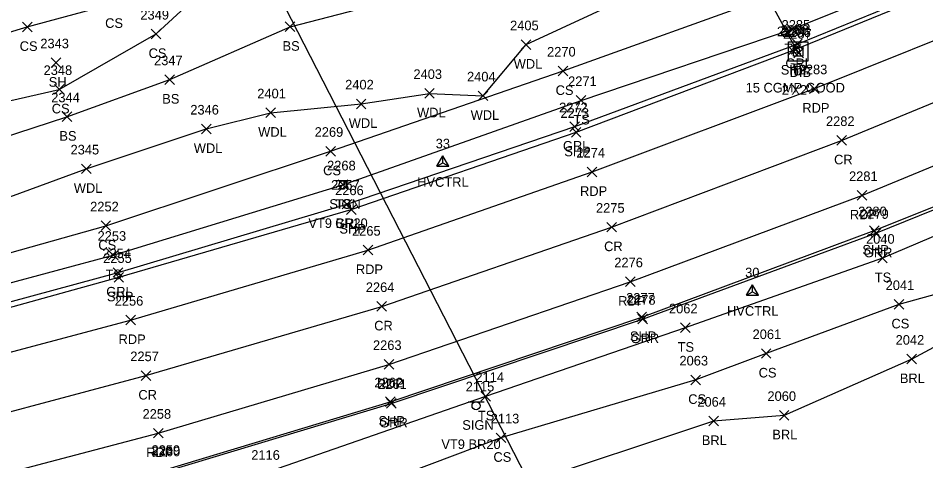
# Model space of a CAD drawing. Extents: x 1502194 to 1507887, y 142265 to 144150.
# Drawn here: x 1506653.1 to 1506842, y 143470.6 to 143562.8 of the extents above; entities that cross this region are included whole.
import ezdxf

# ---------------------------------------------------------------- set-up
doc = ezdxf.new("R2010")
doc.units = 0
for name, color, linetype in [('C_A', 7, 'Continuous'), ('C_I', 7, 'Continuous'), ('CPSM', 7, 'Continuous'), ('D_A', 7, 'Continuous'), ('D_C', 7, 'Continuous'), ('D_I', 7, 'Continuous'), ('D_TIC', 7, 'Continuous'), ('DCP', 7, 'Continuous'), ('DS', 7, 'Continuous'), ('L_A', 7, 'Continuous'), ('L_I', 7, 'Continuous'), ('L_TIC', 7, 'Continuous'), ('LABL', 7, 'Continuous'), ('LAWA', 7, 'Continuous'), ('LELB', 7, 'Continuous'), ('P_A', 7, 'Continuous'), ('P_I', 7, 'Continuous'), ('P_TIC', 7, 'Continuous'), ('PET', 7, 'Continuous'), ('PRC', 7, 'Continuous'), ('PSP', 7, 'Continuous'), ('R_A', 7, 'Continuous'), ('R_I', 7, 'Continuous'), ('R_TIC', 7, 'Continuous'), ('RGR', 7, 'Continuous'), ('S_A', 7, 'Continuous'), ('S_C', 7, 'Continuous'), ('S_I', 7, 'Continuous'), ('SSGN', 7, 'Continuous')]:
    doc.layers.add(name, color=color, linetype=linetype)

msp = doc.modelspace()

# ---------------------------------------------------------------- linework, layer by layer
at = {"layer": 'CPSM'}
for p, q in [((1506740.16, 143531.98), (1506741.41, 143534.15)), ((1506742.66, 143531.98), (1506741.41, 143534.15)), ((1506741.41, 143532.7), (1506741.41, 143534.15)), ((1506740.16, 143531.98), (1506741.41, 143532.7)), ((1506740.16, 143531.98), (1506742.66, 143531.98)), ((1506741.41, 143532.7), (1506741.41, 143532.7)), ((1506741.41, 143532.7), (1506742.66, 143531.98)), ((1506804.65, 143505.13), (1506805.9, 143507.3)), ((1506807.15, 143505.13), (1506805.9, 143507.3)), ((1506805.9, 143505.85), (1506805.9, 143507.3)), ((1506804.65, 143505.13), (1506805.9, 143505.85)), ((1506805.9, 143505.85), (1506805.9, 143505.85)), ((1506805.9, 143505.85), (1506807.15, 143505.13)), ((1506804.65, 143505.13), (1506807.15, 143505.13))]:
    msp.add_line(p, q, dxfattribs=at)
at = {"layer": 'D_TIC'}
for points in [[(1506813.95, 143555.34), (1506815.95, 143557.34)], [(1506815.95, 143555.34), (1506813.95, 143557.34)], [(1506814.51, 143554.57), (1506816.51, 143556.57)], [(1506816.51, 143554.57), (1506814.51, 143556.57)]]:
    msp.add_lwpolyline(points, dxfattribs=at)
at = {"layer": 'DCP'}
for points in [[(1506814.95, 143556.34), (1506782.88, 143615.38)], [(1506777.4, 143431.12), (1506698.03, 143585.85)]]:
    msp.add_lwpolyline(points, dxfattribs=at)
at = {"layer": 'DS'}
for p, q in [((1506813.38, 143557.88), (1506817.38, 143557.88)), ((1506813.38, 143553.88), (1506813.38, 143557.88)), ((1506814.38, 143554.88), (1506814.38, 143556.88)), ((1506814.38, 143556.88), (1506816.38, 143556.88)), ((1506816.38, 143556.88), (1506816.38, 143554.88)), ((1506817.38, 143557.88), (1506817.38, 143553.88)), ((1506816.38, 143554.88), (1506814.38, 143554.88)), ((1506815.39, 143555.88), (1506815.39, 143555.88)), ((1506815.39, 143555.88), (1506815.39, 143555.88)), ((1506817.38, 143553.88), (1506813.38, 143553.88))]:
    msp.add_line(p, q, dxfattribs=at)
at = {"layer": 'L_TIC'}
for points in [[(1506653.94, 143560), (1506655.94, 143562)], [(1506655.94, 143560), (1506653.94, 143562)], [(1506708.64, 143560.03), (1506710.64, 143562.03)], [(1506710.64, 143560.03), (1506708.64, 143562.03)], [(1506680.76, 143558.52), (1506682.76, 143560.52)], [(1506682.76, 143558.52), (1506680.76, 143560.52)], [(1506813.12, 143559.53), (1506815.12, 143561.53)], [(1506815.12, 143559.53), (1506813.12, 143561.53)], [(1506757.77, 143556.3), (1506759.77, 143558.3)], [(1506759.77, 143556.3), (1506757.77, 143558.3)], [(1506659.93, 143552.54), (1506661.93, 143554.54)], [(1506661.93, 143552.54), (1506659.93, 143554.54)], [(1506765.47, 143550.82), (1506767.47, 143552.82)], [(1506767.47, 143550.82), (1506765.47, 143552.82)], [(1506683.6, 143549.02), (1506685.6, 143551.02)], [(1506685.6, 143549.02), (1506683.6, 143551.02)], [(1506660.61, 143546.98), (1506662.61, 143548.98)], [(1506662.61, 143546.98), (1506660.61, 143548.98)], [(1506737.66, 143546.16), (1506739.66, 143548.16)], [(1506739.66, 143546.16), (1506737.66, 143548.16)], [(1506748.81, 143545.64), (1506750.81, 143547.64)], [(1506750.81, 143545.64), (1506748.81, 143547.64)], [(1506723.44, 143543.97), (1506725.44, 143545.97)], [(1506725.44, 143543.97), (1506723.44, 143545.97)], [(1506769.21, 143544.68), (1506771.21, 143546.68)], [(1506771.21, 143544.68), (1506769.21, 143546.68)], [(1506662.2, 143541.3), (1506664.2, 143543.3)], [(1506664.2, 143541.3), (1506662.2, 143543.3)], [(1506704.6, 143542.12), (1506706.6, 143544.12)], [(1506706.6, 143542.12), (1506704.6, 143544.12)], [(1506691.19, 143538.75), (1506693.19, 143540.75)], [(1506693.19, 143538.75), (1506691.19, 143540.75)], [(1506717.08, 143534.11), (1506719.08, 143536.11)], [(1506719.08, 143534.11), (1506717.08, 143536.11)], [(1506666.22, 143530.44), (1506668.22, 143532.44)], [(1506668.22, 143530.44), (1506666.22, 143532.44)], [(1506719.65, 143527.12), (1506721.65, 143529.12)], [(1506721.65, 143527.12), (1506719.65, 143529.12)], [(1506670.3, 143518.58), (1506672.3, 143520.58)], [(1506672.3, 143518.58), (1506670.3, 143520.58)], [(1506671.84, 143512.46), (1506673.84, 143514.46)], [(1506673.84, 143512.46), (1506671.84, 143514.46)], [(1506831.93, 143511.84), (1506833.93, 143513.84)], [(1506833.93, 143511.84), (1506831.93, 143513.84)], [(1506835.36, 143502.21), (1506837.36, 143504.21)], [(1506837.36, 143502.21), (1506835.36, 143504.21)], [(1506790.89, 143497.35), (1506792.89, 143499.35)], [(1506792.89, 143497.35), (1506790.89, 143499.35)], [(1506807.72, 143491.99), (1506809.72, 143493.99)], [(1506809.72, 143491.99), (1506807.72, 143493.99)], [(1506838.01, 143490.82), (1506840.01, 143492.82)], [(1506840.01, 143490.82), (1506838.01, 143492.82)], [(1506793.07, 143486.49), (1506795.07, 143488.49)], [(1506795.07, 143486.49), (1506793.07, 143488.49)], [(1506749.34, 143483.06), (1506751.34, 143485.06)], [(1506751.34, 143483.06), (1506749.34, 143485.06)], [(1506811.47, 143479.11), (1506813.47, 143481.11)], [(1506813.47, 143479.11), (1506811.47, 143481.11)], [(1506796.79, 143477.92), (1506798.79, 143479.92)], [(1506798.79, 143477.92), (1506796.79, 143479.92)], [(1506752.53, 143474.43), (1506754.53, 143476.43)], [(1506754.53, 143474.43), (1506752.53, 143476.43)]]:
    msp.add_lwpolyline(points, dxfattribs=at)
at = {"layer": 'LABL'}
msp.add_lwpolyline([(1506925.15, 143533.52), (1506885.27, 143516.72), (1506839.01, 143491.82), (1506812.47, 143480.11), (1506797.79, 143478.92), (1506756.88, 143465.31), (1506714.98, 143450.06), (1506660.24, 143438.77), (1506613.3, 143423.94), (1506616.52, 143414.64)], dxfattribs=at)
at = {"layer": 'LAWA'}
msp.add_lwpolyline([(1506522.71, 143485.76), (1506572.06, 143503.17), (1506623.68, 143515.47), (1506667.22, 143531.44), (1506692.19, 143539.75), (1506705.6, 143543.12), (1506724.44, 143544.97), (1506738.66, 143547.16), (1506749.81, 143546.64), (1506758.77, 143557.3), (1506807.57, 143579.94), (1506846.79, 143592.4), (1506896.99, 143614.38)], dxfattribs=at)
at = {"layer": 'LELB'}
for points in [[(1506624.13, 143555.62), (1506640.38, 143556.63), (1506654.94, 143561), (1506672.72, 143565.79), (1506679.72, 143575.67), (1506695.05, 143577.62), (1506699.47, 143577.91), (1506701.5, 143575.19), (1506703.76, 143575.39), (1506707.13, 143577.97), (1506705.55, 143581.26), (1506716.61, 143587.23), (1506735.68, 143602.47), (1506756.62, 143603.39), (1506780.29, 143609.03), (1506830.83, 143625.99), (1506880.34, 143648.95)], [(1506517.85, 143501.34), (1506567.89, 143522.62), (1506612.11, 143536.7), (1506661.61, 143547.98), (1506681.76, 143559.52), (1506695.53, 143572.24), (1506704.85, 143572.91), (1506725.52, 143573.91), (1506746.5, 143587.18), (1506797.75, 143604.14), (1506837.79, 143614.31), (1506888.27, 143631.28)], [(1506520.26, 143493.12), (1506571.84, 143512.42), (1506617.89, 143527.46), (1506663.2, 143542.3), (1506684.6, 143550.02), (1506709.64, 143561.03), (1506743.74, 143569.88), (1506756.3, 143575.97), (1506802.67, 143594.79), (1506845.42, 143601.65), (1506896.99, 143614.38)], [(1506527.12, 143479.02), (1506576.48, 143493.75), (1506624.1, 143506.32), (1506671.3, 143519.58), (1506718.08, 143535.11), (1506766.47, 143551.82), (1506810.91, 143567.85), (1506852.21, 143584.27), (1506899, 143603.69)], [(1506528.28, 143476.03), (1506576.44, 143487.76), (1506625.32, 143500.66), (1506672.84, 143513.46), (1506720.65, 143528.12), (1506770.21, 143545.68), (1506814.12, 143560.53), (1506853.98, 143576.57), (1506901.25, 143597.01)], [(1506920.49, 143550.15), (1506879.81, 143532.73), (1506832.93, 143512.84), (1506791.89, 143498.35), (1506750.34, 143484.06), (1506703.75, 143467.85), (1506654.25, 143455.79), (1506605.88, 143441.31), (1506565.5, 143431.73), (1506554.53, 143418.24), (1506550.8, 143411.14), (1506553.36, 143401.15), (1506568.06, 143393.58), (1506589.98, 143377.59)], [(1506885.27, 143516.72), (1506836.36, 143503.21), (1506808.72, 143492.99), (1506794.07, 143487.49), (1506753.53, 143475.43), (1506709.32, 143458.78), (1506657.01, 143447.54), (1506608.42, 143435.74), (1506565.83, 143422.65), (1506556.41, 143414.68), (1506554.63, 143405.1), (1506570.25, 143400.38), (1506594.37, 143381.91)]]:
    msp.add_lwpolyline(points, dxfattribs=at)
at = {"layer": 'P_TIC'}
for points in [[(1506813.23, 143555.06), (1506815.23, 143557.06)], [(1506815.23, 143555.06), (1506813.23, 143557.06)], [(1506817.76, 143547.14), (1506819.76, 143549.14)], [(1506819.76, 143547.14), (1506817.76, 143549.14)], [(1506768.18, 143538.06), (1506770.18, 143540.06)], [(1506770.18, 143538.06), (1506768.18, 143540.06)], [(1506823.43, 143536.37), (1506825.43, 143538.37)], [(1506825.43, 143536.37), (1506823.43, 143538.37)], [(1506771.5, 143529.8), (1506773.5, 143531.8)], [(1506773.5, 143529.8), (1506771.5, 143531.8)], [(1506827.66, 143524.9), (1506829.66, 143526.9)], [(1506829.66, 143524.9), (1506827.66, 143526.9)], [(1506721.38, 143521.96), (1506723.38, 143523.96)], [(1506723.38, 143521.96), (1506721.38, 143523.96)], [(1506775.57, 143518.3), (1506777.57, 143520.3)], [(1506777.57, 143518.3), (1506775.57, 143520.3)], [(1506830.22, 143517.57), (1506832.22, 143519.57)], [(1506832.22, 143517.57), (1506830.22, 143519.57)], [(1506724.85, 143513.52), (1506726.85, 143515.52)], [(1506726.85, 143513.52), (1506724.85, 143515.52)], [(1506673.01, 143507.85), (1506675.01, 143509.85)], [(1506675.01, 143507.85), (1506673.01, 143509.85)], [(1506779.44, 143506.94), (1506781.44, 143508.94)], [(1506781.44, 143506.94), (1506779.44, 143508.94)], [(1506727.72, 143501.79), (1506729.72, 143503.79)], [(1506729.72, 143501.79), (1506727.72, 143503.79)], [(1506781.84, 143499.58), (1506783.84, 143501.58)], [(1506783.84, 143499.58), (1506781.84, 143501.58)], [(1506675.46, 143498.95), (1506677.46, 143500.95)], [(1506677.46, 143498.95), (1506675.46, 143500.95)], [(1506729.21, 143489.72), (1506731.21, 143491.72)], [(1506731.21, 143489.72), (1506729.21, 143491.72)], [(1506678.65, 143487.39), (1506680.65, 143489.39)], [(1506680.65, 143487.39), (1506678.65, 143489.39)], [(1506729.5, 143481.95), (1506731.5, 143483.95)], [(1506731.5, 143481.95), (1506729.5, 143483.95)], [(1506681.2, 143475.4), (1506683.2, 143477.4)], [(1506683.2, 143475.4), (1506681.2, 143477.4)]]:
    msp.add_lwpolyline(points, dxfattribs=at)
at = {"layer": 'PET'}
for points in [[(1506529.33, 143464.2), (1506579.89, 143475.85), (1506626.64, 143486.68), (1506676.46, 143499.95), (1506725.85, 143514.52), (1506772.5, 143530.8), (1506818.76, 143548.14), (1506859.25, 143564.41), (1506906.68, 143584.91)], [(1506536.88, 143441.34), (1506584.71, 143452.38), (1506632.33, 143463.25), (1506682.2, 143476.4), (1506730.21, 143490.72), (1506780.44, 143507.94), (1506828.66, 143525.9), (1506867.29, 143541.82), (1506915.31, 143562.43)]]:
    msp.add_lwpolyline(points, dxfattribs=at)
at = {"layer": 'PRC'}
msp.add_lwpolyline([(1506532.45, 143452.54), (1506582.29, 143463.86), (1506629.68, 143475.08), (1506679.65, 143488.39), (1506728.72, 143502.79), (1506776.57, 143519.3), (1506824.43, 143537.37), (1506862.78, 143553.15), (1506910.97, 143573.95)], dxfattribs=at)
at = {"layer": 'PSP'}
for points in [[(1506528.1, 143471.41), (1506577.64, 143482.92), (1506624.2, 143495.08), (1506674.01, 143508.85), (1506722.38, 143522.96), (1506769.18, 143539.06), (1506814.23, 143556.06), (1506856.23, 143573.29), (1506902.36, 143593.17)], [(1506542.57, 143434.01), (1506586.24, 143444.04), (1506633.16, 143454.96), (1506684.08, 143468.88), (1506730.5, 143482.95), (1506782.84, 143500.58), (1506831.22, 143518.57), (1506871.13, 143534.59), (1506917.52, 143554.61)]]:
    msp.add_lwpolyline(points, dxfattribs=at)
at = {"layer": 'R_TIC'}
for points in [[(1506814.19, 143556.42), (1506816.19, 143558.42)], [(1506816.19, 143556.42), (1506814.19, 143558.42)], [(1506767.89, 143539.23), (1506769.89, 143541.23)], [(1506769.89, 143539.23), (1506767.89, 143541.23)], [(1506720.49, 143523.09), (1506722.49, 143525.09)], [(1506722.49, 143523.09), (1506720.49, 143525.09)], [(1506830.56, 143517.03), (1506832.56, 143519.03)], [(1506832.56, 143517.03), (1506830.56, 143519.03)], [(1506672.85, 143508.85), (1506674.85, 143510.85)], [(1506674.85, 143508.85), (1506672.85, 143510.85)], [(1506782.02, 143499.15), (1506784.02, 143501.15)], [(1506784.02, 143499.15), (1506782.02, 143501.15)], [(1506729.71, 143481.6), (1506731.71, 143483.6)], [(1506731.71, 143481.6), (1506729.71, 143483.6)]]:
    msp.add_lwpolyline(points, dxfattribs=at)
at = {"layer": 'RGR'}
for points in [[(1506528.09, 143471.93), (1506577.33, 143484.15), (1506624.99, 143496.57), (1506673.85, 143509.85), (1506721.49, 143524.09), (1506768.89, 143540.23), (1506815.19, 143557.42), (1506856.11, 143574.12), (1506902.1, 143593.94)], [(1506543.48, 143429.76), (1506556.69, 143434.17), (1506568.66, 143438.23), (1506586.4, 143443.43), (1506633.04, 143454.6), (1506684.23, 143468.58), (1506730.71, 143482.6), (1506783.02, 143500.15), (1506831.56, 143518.03), (1506871.47, 143534.19), (1506917.7, 143554.27)]]:
    msp.add_lwpolyline(points, dxfattribs=at)
at = {"layer": 'SSGN'}
for p, q in [((1506719.03, 143528.98), (1506722.36, 143528.98)), ((1506720.67, 143528.14), (1506720.67, 143528.14)), ((1506746.69, 143482.95), (1506750.03, 143482.95)), ((1506748.34, 143482.12), (1506748.34, 143482.12))]:
    msp.add_line(p, q, dxfattribs=at)
for centre in [(1506720.67, 143528.14), (1506748.34, 143482.12)]:
    msp.add_circle(centre, 0.833, dxfattribs=at)

# ---------------------------------------------------------------- texts
at = {"layer": 'C_A'}
for p in [(1506736.11, 143527.7), (1506800.59, 143500.85)]:
    msp.add_text('HVCTRL', height=2, dxfattribs=at).set_placement(p)
at = {"layer": 'C_I'}
for s, p in [('33', (1506739.95, 143535.7)), ('30', (1506804.35, 143508.85))]:
    msp.add_text(s, height=2, dxfattribs=at).set_placement(p)
at = {"layer": 'D_A'}
for s, p in [('DIB', (1506813.61, 143550.57)), ('P', (1506814.33, 143551.34)), ('DI', (1506814.44, 143550.88))]:
    msp.add_text(s, height=2, dxfattribs=at).set_placement(p)
at = {"layer": 'D_C'}
for s, p in [('15 CGMP GOOD', (1506804.45, 143547.34)), ("2'X2'", (1506811.98, 143546.88))]:
    msp.add_text(s, height=2, dxfattribs=at).set_placement(p)
at = {"layer": 'D_I'}
for s, p in [('2288', (1506811.69, 143559.34)), ('2286', (1506812.07, 143558.88)), ('2287', (1506812.25, 143558.57))]:
    msp.add_text(s, height=2, dxfattribs=at).set_placement(p)
at = {"layer": 'L_A'}
for s, p in [('CS', (1506671.16, 143560.79)), ('CS', (1506653.38, 143556)), ('CS', (1506680.2, 143554.52)), ('BS', (1506708.08, 143556.03)), ('TS', (1506812.53, 143555.53)), ('WDL', (1506756.19, 143552.3)), ('SH', (1506659.42, 143548.54)), ('CS', (1506764.91, 143546.82)), ('BS', (1506683.04, 143545.02)), ('CS', (1506660.05, 143542.98)), ('WDL', (1506736.07, 143542.16)), ('WDL', (1506747.23, 143541.64)), ('WDL', (1506721.86, 143539.97)), ('TS', (1506768.62, 143540.68)), ('BS', (1506661.64, 143537.3)), ('WDL', (1506703.01, 143538.12)), ('WDL', (1506689.61, 143534.75)), ('CS', (1506716.52, 143530.11)), ('WDL', (1506664.64, 143526.44)), ('TS', (1506719.06, 143523.12)), ('CS', (1506669.74, 143514.58)), ('TS', (1506671.25, 143508.46)), ('TS', (1506831.34, 143507.84)), ('CS', (1506834.8, 143498.21)), ('TS', (1506790.3, 143493.35)), ('CS', (1506807.16, 143487.99)), ('BRL', (1506836.55, 143486.82)), ('CS', (1506792.51, 143482.49)), ('TS', (1506748.74, 143479.06)), ('BRL', (1506810.01, 143475.11)), ('BRL', (1506795.33, 143473.92)), ('CS', (1506751.97, 143470.43))]:
    msp.add_text(s, height=2, dxfattribs=at).set_placement(p)
at = {"layer": 'L_I'}
for s, p in [('2349', (1506678.49, 143562.52)), ('2405', (1506755.43, 143560.3)), ('2343', (1506657.67, 143556.54)), ('2270', (1506763.13, 143554.82)), ('2347', (1506681.34, 143553.02)), ('2348', (1506658.35, 143550.98)), ('2403', (1506735.32, 143550.16)), ('2404', (1506746.47, 143549.64)), ('2271', (1506767.51, 143548.68)), ('2402', (1506721.11, 143547.97)), ('2344', (1506659.94, 143545.3)), ('2401', (1506702.82, 143546.12)), ('2346', (1506688.88, 143542.75)), ('2269', (1506714.76, 143538.11)), ('2345', (1506663.96, 143534.44)), ('2268', (1506717.35, 143531.12)), ('2252', (1506668.04, 143522.58)), ('2253', (1506669.58, 143516.46)), ('2040', (1506829.51, 143515.84)), ('2041', (1506833.59, 143506.21)), ('2062', (1506788.5, 143501.35)), ('2061', (1506805.9, 143495.99)), ('2042', (1506835.67, 143494.82)), ('2063', (1506790.68, 143490.49)), ('2114', (1506748.21, 143487.06)), ('2060', (1506808.99, 143483.11)), ('2064', (1506794.4, 143481.92)), ('2113', (1506751.4, 143478.43)), ('2116', (1506701.57, 143470.85))]:
    msp.add_text(s, height=2, dxfattribs=at).set_placement(p)
at = {"layer": 'P_A'}
for s, p in [('SHP', (1506811.76, 143551.06)), ('RDP', (1506816.25, 143543.14)), ('SHP', (1506766.72, 143534.06)), ('CR', (1506822.86, 143532.37)), ('RDP', (1506769.99, 143525.8)), ('RDP', (1506826.15, 143520.9)), ('SHP', (1506719.91, 143517.96)), ('CR', (1506775, 143514.3)), ('SHP', (1506828.75, 143513.57)), ('RDP', (1506723.34, 143509.52)), ('SHP', (1506671.54, 143503.85)), ('RDP', (1506777.93, 143502.94)), ('CR', (1506727.15, 143497.79)), ('RDP', (1506673.95, 143494.95)), ('SHP', (1506780.37, 143495.58)), ('RDP', (1506727.7, 143485.72)), ('CR', (1506678.08, 143483.39)), ('SHP', (1506728.04, 143477.95)), ('RDP', (1506679.69, 143471.4))]:
    msp.add_text(s, height=2, dxfattribs=at).set_placement(p)
at = {"layer": 'P_I'}
for s, p in [('2284', (1506810.97, 143559.06)), ('2283', (1506815.5, 143551.14)), ('2273', (1506765.92, 143542.06)), ('2282', (1506821.17, 143540.37)), ('2274', (1506769.24, 143533.8)), ('2281', (1506825.97, 143528.9)), ('2266', (1506719.02, 143525.96)), ('2275', (1506773.31, 143522.3)), ('2280', (1506827.87, 143521.57)), ('2265', (1506722.54, 143517.52)), ('2255', (1506670.75, 143511.85)), ('2276', (1506777.12, 143510.94)), ('2264', (1506725.41, 143505.79)), ('2277', (1506779.58, 143503.58)), ('2256', (1506673.15, 143502.95)), ('2263', (1506726.9, 143493.72)), ('2257', (1506676.39, 143491.39)), ('2262', (1506727.19, 143485.95)), ('2258', (1506678.94, 143479.4)), ('2259', (1506680.81, 143471.88))]:
    msp.add_text(s, height=2, dxfattribs=at).set_placement(p)
at = {"layer": 'R_A'}
for s, p in [('GRL', (1506812.74, 143552.42)), ('GRL', (1506766.43, 143535.23)), ('GRL', (1506719.03, 143519.09)), ('GRR', (1506829.05, 143513.03)), ('GRL', (1506671.39, 143504.85)), ('GRR', (1506780.51, 143495.15)), ('GRR', (1506728.2, 143477.6))]:
    msp.add_text(s, height=2, dxfattribs=at).set_placement(p)
at = {"layer": 'R_I'}
for s, p in [('2285', (1506811.93, 143560.42)), ('2272', (1506765.63, 143543.23)), ('2267', (1506718.18, 143527.09)), ('2279', (1506828.29, 143521.03)), ('2254', (1506670.59, 143512.85)), ('2278', (1506779.76, 143503.15)), ('2261', (1506727.97, 143485.6)), ('2260', (1506680.84, 143471.58))]:
    msp.add_text(s, height=2, dxfattribs=at).set_placement(p)
at = {"layer": 'S_A'}
for p in [(1506717.81, 143523.12), (1506745.48, 143477.1)]:
    msp.add_text('SIGN', height=2, dxfattribs=at).set_placement(p)
at = {"layer": 'S_C'}
for p in [(1506713.46, 143519.12), (1506741.13, 143473.1)]:
    msp.add_text('VT9 BR20', height=2, dxfattribs=at).set_placement(p)
at = {"layer": 'S_I'}
for s, p in [('2268', (1506717.35, 143531.12)), ('2115', (1506746.19, 143485.1))]:
    msp.add_text(s, height=2, dxfattribs=at).set_placement(p)

doc.saveas('drawing.dxf')
